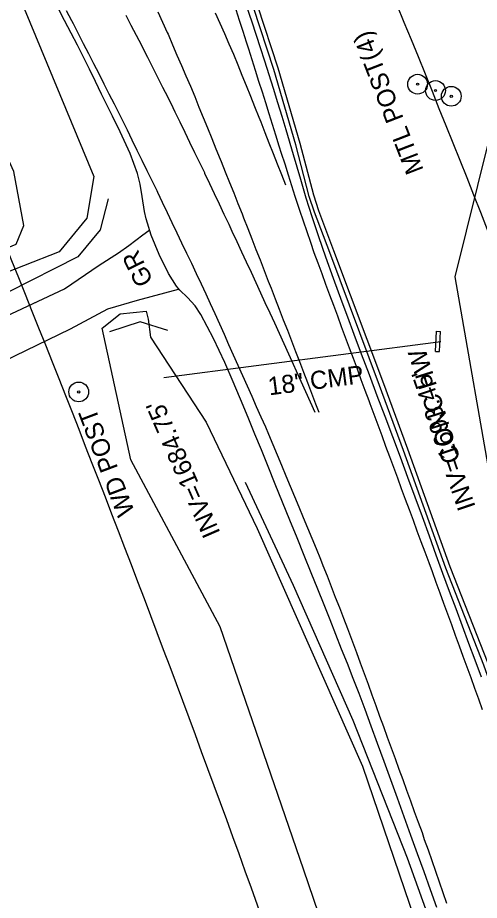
# Model space of a CAD drawing. Extents: x 472260 to 482161, y 489063 to 507124.
# Drawn here: x 480949.2 to 481051, y 492689.3 to 492884.2 of the extents above; entities that cross this region are included whole.
import ezdxf

# ---------------------------------------------------------------- set-up
doc = ezdxf.new("R2010")
doc.units = 0
for name, color, linetype in [('Exist Structure Minor Drop Inlet Cogo Elevation', 7, 'Continuous'), ('Exist Structure Minor Pipes CMP 30 Inch', 7, 'Continuous'), ('Prop Drainage Structure Catch Basin Convert From Junction Box Label', 7, 'Continuous'), ('Prop Drainage Structure Drop Inlet Grate 2 Narrow Slots and Sag Grates 840 24 CELL', 7, 'Continuous'), ('Prop Drainage Structure Pipe RCP 18in Class III', 7, 'Continuous'), ('Prop Drainage Structure Pipe RCP 30in Class III', 7, 'Continuous'), ('Prop Drainage Structure Pipe RCP 66in Class IV', 7, 'Continuous'), ('Prop Drainage Structure Pipe RCP 66in Class IV Label', 7, 'Continuous'), ('Prop Drainage Structure Pipe RCP 72in Class III', 7, 'Continuous'), ('Prop Drainage Structure Pipe Stub Out CELL', 7, 'Continuous'), ('Prop Drainage Structure Pipe Welded Steel 72in Label', 7, 'Continuous'), ('Prop Drainage Structure Plot Symbol 20 Scale CELL', 7, 'Continuous'), ('Prop Drainage Structure Plot Symbol 50 Scale', 7, 'Continuous'), ('Prop Drainage Structure Plot Symbol 50 Scale CELL', 7, 'Continuous'), ('Prop Drainage Structure Tops and Inverts LABEL', 7, 'Continuous'), ('Prop Earthen Structure False Sump Label', 7, 'Continuous'), ('Prop Erosion Rip Rap Pad at Outlet Label', 7, 'Continuous')]:
    doc.layers.add(name, color=color, linetype=linetype)

msp = doc.modelspace()

# ---------------------------------------------------------------- linework, layer by layer
at = {"layer": 'Exist Structure Minor Drop Inlet Cogo Elevation'}
for radius in [3954.58, 3854.58]:
    msp.add_arc((477373.51, 491387.79), radius, 18.70399, 22.51531, dxfattribs=at)
at = {"layer": 'Prop Drainage Structure Catch Basin Convert From Junction Box Label'}
for points in [[(481010.55, 492856.1), (481005.68, 492872.7), (481001.19, 492886.38), (480997.42, 492897.8), (480991.82, 492911.64), (480986.19, 492925.13), (480980.52, 492938.19), (480975.01, 492949.7), (480968.57, 492962.71), (480963.05, 492972.48), (480958.15, 492980.77), (480950.82, 492991.98), (480939.98, 493008.84), (480927.18, 493026.88)], [(481011.51, 492856.38), (481006.63, 492872.99), (481002.14, 492886.69), (480998.36, 492898.14), (480992.74, 492912.02), (480987.11, 492925.52), (480981.43, 492938.61), (480975.91, 492950.13), (480969.46, 492963.18), (480963.91, 492972.98), (480959, 492981.3), (480951.66, 492992.52), (480940.81, 493009.4), (480929.67, 493025.1)], [(481161.88, 492420.66), (481155.74, 492438.52), (481140.65, 492483.95), (481128.4, 492520.35), (481115.63, 492558.71), (481105.51, 492588.85), (481093.17, 492625.43), (481084.14, 492652.32), (481071.54, 492688.73), (481063.8, 492710.99), (481052.94, 492741.58), (481044.61, 492762.94), (481035.26, 492788.9), (481029.93, 492803.33), (481018.96, 492832.67), (481015.61, 492841.54), (481014.49, 492844.96), (481011.51, 492856.38)], [(481130.21, 492511.53), (481127.45, 492520.03), (481114.68, 492558.39), (481104.56, 492588.53), (481092.22, 492625.11), (481083.19, 492652), (481070.59, 492688.41), (481062.85, 492710.66), (481052, 492741.23), (481043.67, 492762.58), (481034.33, 492788.56), (481029, 492802.98), (481018.03, 492832.32), (481014.67, 492841.21), (481013.53, 492844.68), (481010.55, 492856.1)]]:
    msp.add_lwpolyline(points, dxfattribs=at)
at = {"layer": 'Prop Drainage Structure Drop Inlet Grate 2 Narrow Slots and Sag Grates 840 24 CELL'}
for points in [[(481043.89, 492688.55), (481043.07, 492690.9), (481042.25, 492693.25), (481041.43, 492695.6), (481040.61, 492697.96), (481039.79, 492700.31), (481038.97, 492702.66), (481038.46, 492704.14), (481037.61, 492706.48), (481036.76, 492708.82), (481035.91, 492711.16), (481035.06, 492713.51), (481034.21, 492715.85), (481033.36, 492718.19), (481032.51, 492720.53), (481031.65, 492722.87), (481030.8, 492725.21), (481029.95, 492727.55), (481029.1, 492729.89), (481028.25, 492732.23), (481027.4, 492734.58), (481026.55, 492736.92), (481025.7, 492739.26), (481024.85, 492741.6), (481024, 492743.94), (481023.15, 492746.28), (481022.93, 492746.88), (481022.03, 492749.2), (481021.13, 492751.52), (481020.23, 492753.85), (481019.32, 492756.17), (481018.42, 492758.49), (481017.52, 492760.81), (481016.62, 492763.13), (481016.07, 492764.54), (481015.11, 492766.85), (481014.15, 492769.15), (481013.2, 492771.45), (481012.24, 492773.75), (481011.29, 492776.05), (481010.33, 492778.35), (481009.37, 492780.66), (481008.42, 492782.96), (481007.46, 492785.26), (481006.5, 492787.56), (481005.55, 492789.86), (481004.59, 492792.16), (481003.95, 492793.71), (481002.93, 492795.99), (481001.91, 492798.26), (481000.89, 492800.54), (480999.88, 492802.81), (480998.86, 492805.09), (480997.84, 492807.36), (480996.83, 492809.64), (480995.81, 492811.91), (480994.79, 492814.19), (480993.77, 492816.46), (480992.76, 492818.74), (480991.74, 492821.01), (480990.81, 492823.1), (480989.73, 492825.35), (480988.66, 492827.6), (480987.59, 492829.85), (480986.52, 492832.1), (480985.45, 492834.34), (480984.38, 492836.59), (480983.31, 492838.84), (480982.24, 492841.09), (480981.16, 492843.34), (480980.09, 492845.59), (480979.95, 492845.9), (480978.85, 492848.14), (480977.76, 492850.37), (480976.67, 492852.61), (480975.58, 492854.85), (480974.49, 492857.09), (480973.4, 492859.33), (480972.3, 492861.57), (480971.68, 492862.85), (480970.55, 492865.07), (480969.41, 492867.29), (480968.28, 492869.51), (480967.15, 492871.73), (480966.02, 492873.95), (480964.89, 492876.17), (480963.75, 492878.38), (480962.62, 492880.6), (480961.49, 492882.82), (480961.15, 492883.48), (480959.95, 492885.66)], [(480980.12, 492885.47), (480981.15, 492883.2), (480982.17, 492880.93), (480982.37, 492880.49), (480983.36, 492878.19), (480984.34, 492875.9), (480985.32, 492873.61), (480986.31, 492871.32), (480987.29, 492869.03), (480988.27, 492866.75), (480989.2, 492864.44), (480990.14, 492862.13), (480991.08, 492859.82), (480992.01, 492857.51), (480992.95, 492855.2), (480993.88, 492852.89), (480994.08, 492852.42), (480995, 492850.11), (480995.92, 492847.79), (480996.85, 492845.48), (480997.77, 492843.16), (480998.7, 492840.85), (480999.05, 492839.96), (480999.96, 492837.64), (481000.86, 492835.31), (481001.77, 492832.99), (481002.67, 492830.67), (481003.57, 492828.34), (481004.48, 492826.02), (481005.1, 492824.44), (481006, 492822.11), (481006.9, 492819.79), (481007.8, 492817.46), (481008.7, 492815.14), (481009.6, 492812.81), (481010.51, 492810.49), (481011.37, 492808.25), (481012.26, 492805.92), (481013.15, 492803.59), (481014.04, 492801.26), (481014.92, 492798.93), (481015.64, 492797.04)], [(480997.32, 492885.97), (480998.09, 492883.6), (480998.85, 492881.22), (480999.62, 492878.85), (481000.12, 492877.32), (481000.87, 492874.94), (481001.61, 492872.56), (481002.36, 492870.18), (481003.1, 492867.8), (481003.85, 492865.42), (481004.59, 492863.04), (481005.34, 492860.66), (481006.08, 492858.28), (481006.83, 492855.89), (481007.34, 492854.25), (481008.1, 492851.87), (481008.86, 492849.49), (481009.61, 492847.12), (481010.37, 492844.74), (481011.12, 492842.36), (481011.34, 492841.68), (481012.15, 492839.32), (481012.95, 492836.96), (481013.76, 492834.6), (481014.53, 492832.34), (481015.39, 492830), (481016.26, 492827.67), (481017.13, 492825.33), (481017.99, 492822.99), (481018.86, 492820.65), (481019.73, 492818.31), (481020.59, 492815.97), (481021.46, 492813.63), (481022.32, 492811.3), (481023.19, 492808.96), (481024.06, 492806.62), (481024.92, 492804.28), (481025.79, 492801.94), (481026.66, 492799.6), (481026.9, 492798.94), (481027.77, 492796.6), (481028.63, 492794.26), (481029.49, 492791.92), (481030.36, 492789.58), (481031.22, 492787.24), (481032.09, 492784.9), (481032.95, 492782.56), (481033.81, 492780.22), (481034.68, 492777.88), (481035.54, 492775.55), (481036.41, 492773.21), (481037.27, 492770.87), (481038.14, 492768.53), (481039, 492766.19), (481039.86, 492763.85), (481040.59, 492761.88), (481041.44, 492759.54), (481042.3, 492757.2), (481043.15, 492754.86), (481044, 492752.52), (481044.86, 492750.17), (481045.71, 492747.83), (481046.56, 492745.49), (481047.42, 492743.15), (481048.27, 492740.8), (481049.12, 492738.46), (481049.98, 492736.12), (481050.83, 492733.78), (481051.68, 492731.44)], [(481014.79, 492797.02), (481013.77, 492799.3), (481012.75, 492801.57), (481011.74, 492803.85), (481010.72, 492806.12), (481010.05, 492807.62), (481009.01, 492809.89), (481007.98, 492812.15), (481006.94, 492814.42), (481005.91, 492816.68), (481004.87, 492818.95), (481003.83, 492821.22), (481002.85, 492823.37), (481001.8, 492825.63), (481000.75, 492827.89), (480999.7, 492830.15), (480998.65, 492832.41), (480997.6, 492834.67), (480996.55, 492836.93), (480995.84, 492838.48), (480994.78, 492840.73), (480993.71, 492842.98), (480992.65, 492845.24), (480991.59, 492847.49), (480990.52, 492849.74), (480990.46, 492849.87), (480989.38, 492852.11), (480988.29, 492854.35), (480987.21, 492856.6), (480986.12, 492858.84), (480985.04, 492861.08), (480983.95, 492863.33), (480983.49, 492864.28), (480982.37, 492866.51), (480981.25, 492868.73), (480980.13, 492870.96), (480979, 492873.18), (480977.88, 492875.4), (480976.76, 492877.63), (480976.58, 492877.99), (480975.42, 492880.2), (480974.27, 492882.41), (480973.11, 492884.62)], [(481008.36, 492847.15), (481007.45, 492849.47), (481006.54, 492851.79), (481005.62, 492854.11), (481004.71, 492856.43), (481003.8, 492858.75), (481002.88, 492861.07), (481002.47, 492862.13), (481001.54, 492864.45), (481000.61, 492866.76), (480999.68, 492869.08), (480998.75, 492871.39), (480997.83, 492873.71), (480996.88, 492876.05), (480995.87, 492878.34), (480994.87, 492880.62), (480993.86, 492882.9), (480992.85, 492885.18)]]:
    msp.add_lwpolyline(points, dxfattribs=at)
at = {"layer": 'Prop Drainage Structure Pipe RCP 18in Class III'}
for points in [[(480971.46, 492832.22), (480973.7, 492833.83), (480976.82, 492836.21), (480978.15, 492837.18)], [(480834.87, 492771.53), (480840.55, 492773.82), (480848.56, 492777.43), (480856.84, 492781.47), (480867, 492786.25), (480881.95, 492792.54), (480895.21, 492798.25), (480910.39, 492803.87), (480922.36, 492808.33), (480936.91, 492813.83), (480946.64, 492818.22), (480959.55, 492824.32), (480967.21, 492829.54), (480971.46, 492832.22)], [(480984.63, 492824.12), (480975.58, 492821.69)], [(480975.58, 492821.69), (480969.05, 492819.78), (480960.81, 492815.39), (480946.05, 492808.24), (480932.6, 492802.73), (480915.65, 492797.03), (480899.26, 492791.61), (480885.53, 492786.06), (480876.07, 492781.56), (480866.73, 492776.38), (480854.01, 492768.4)]]:
    msp.add_lwpolyline(points, dxfattribs=at)
at = {"layer": 'Prop Drainage Structure Pipe RCP 66in Class IV'}
msp.add_line((480981.44, 492804.69), (481042.53, 492812.66), dxfattribs=at)
at = {"layer": 'Prop Drainage Structure Pipe RCP 72in Class III'}
for points in [[(480969.15, 492844.19), (480967.38, 492837.31), (480962.49, 492831.38), (480947.15, 492823.58), (480935.93, 492819.13)], [(480982.3, 492815.09), (480976.24, 492817), (480969.46, 492814.82)]]:
    msp.add_lwpolyline(points, dxfattribs=at)
at = {"layer": 'Prop Drainage Structure Pipe Stub Out CELL'}
for points in [[(480999, 492888.65), (481000.83, 492883.24), (481002.68, 492877.56), (481003.62, 492874.62), (481004.57, 492871.63), (481005.53, 492868.58), (481006.51, 492865.47), (481007.45, 492862.4), (481008.35, 492859.46), (481009.98, 492853.95), (481011.56, 492848.49), (481012.79, 492844.39), (481014.07, 492840.25), (481015.53, 492835.84), (481017.11, 492831.36), (481018.81, 492826.63), (481020.72, 492821.39), (481021.94, 492818.09), (481023.37, 492814.28), (481025, 492809.94), (481026.73, 492805.34), (481028.45, 492800.77), (481030.17, 492796.21), (481031.87, 492791.68), (481033.56, 492787.18), (481035.2, 492782.73), (481036.82, 492778.33), (481038.39, 492773.99), (481039.93, 492769.73), (481041.45, 492765.57), (481042.93, 492761.51), (481044.38, 492757.56), (481045.81, 492753.69), (481047.23, 492749.86), (481048.63, 492746.08), (481050.02, 492742.35), (481051.4, 492738.65)], [(481041.65, 492687.71), (481040.26, 492691.59), (481038.83, 492695.54), (481037.39, 492699.54), (481035.92, 492703.6), (481034.44, 492707.71), (481032.96, 492711.83), (481031.49, 492715.89), (481030.04, 492719.91), (481028.6, 492723.88), (481027.19, 492727.74), (481025.82, 492731.43), (481024.49, 492734.94), (481023.2, 492738.28), (481021.93, 492741.53), (481020.66, 492744.76), (481019.39, 492747.99), (481018.11, 492751.21), (481016.8, 492754.51), (481015.41, 492757.97), (481013.94, 492761.6), (481012.4, 492765.39), (481010.82, 492769.28), (481009.23, 492773.21), (481007.63, 492777.16), (481006.02, 492781.15), (481004.45, 492785.05), (481002.95, 492788.74), (481001.52, 492792.21), (481000.17, 492795.48), (480998.91, 492798.5), (480996.7, 492803.74), (480994.87, 492807.99), (480992.37, 492813.34), (480989.64, 492818.66), (480988.33, 492820.54), (480986.7, 492822.4), (480985.01, 492824.02), (480984.27, 492824.9), (480982.51, 492827.7), (480980.44, 492831.88), (480978.68, 492836.14), (480977.52, 492839.73), (480977.15, 492841.38), (480976.7, 492844.71), (480976.23, 492847.44), (480975.65, 492849.79), (480974.01, 492854.17), (480971.82, 492858.95), (480970.12, 492862.44), (480967.73, 492867.31), (480966.37, 492870.07), (480965.02, 492872.78), (480962.38, 492878.06), (480961.01, 492880.73), (480959.55, 492883.57), (480957.97, 492886.57)]]:
    msp.add_lwpolyline(points, dxfattribs=at)
at = {"layer": 'Prop Drainage Structure Plot Symbol 20 Scale CELL'}
for centre, radius in [((481037.42, 492869.48), 2.18), ((481041.36, 492868.08), 2.18), ((481037.42, 492869.48), 0.24), ((481041.36, 492868.08), 0.24), ((481044.84, 492866.81), 2.18), ((481044.84, 492866.81), 0.24), ((480962.68, 492801.53), 2.18), ((480962.68, 492801.53), 0.24)]:
    msp.add_circle(centre, radius, dxfattribs=at)
at = {"layer": 'Prop Drainage Structure Plot Symbol 50 Scale'}
for p, q in [((481041.39, 492810.46), (481041.61, 492814.91)), ((481041.61, 492814.91), (481042.44, 492814.87)), ((481042.22, 492810.42), (481042.44, 492814.87)), ((481041.39, 492810.46), (481042.22, 492810.42))]:
    msp.add_line(p, q, dxfattribs=at)
at = {"layer": 'Prop Drainage Structure Plot Symbol 50 Scale CELL'}
msp.add_lwpolyline([(481159.92, 492332.85), (481147.67, 492369.02), (481136.31, 492402.63), (481122.19, 492443.94), (481109.37, 492481.77), (481096.99, 492518.51), (481082.03, 492563.66), (481066.9, 492608.24), (481049.63, 492658.22), (481035.22, 492698.61), (481023.2, 492728.97), (481010.06, 492758.78), (480999.42, 492781.5)], dxfattribs=at)
at = {"layer": 'Prop Drainage Structure Tops and Inverts LABEL'}
for points in [[(480941.52, 492831.11), (480948.88, 492834.16), (480950.54, 492838.31), (480948.36, 492850.21), (480929.77, 492891.42), (480918.34, 492912.08), (480925.79, 492919.02), (480932.4, 492916.78), (480949.38, 492889.32), (480965.99, 492849.1), (480964.5, 492839.91), (480958.38, 492832.46), (480942.57, 492826.26)], [(481080.2, 492471.74), (481071.23, 492513.93), (481054.53, 492571.95), (481012.28, 492696.13), (480993.86, 492749.69), (480974.19, 492786.51), (480967.88, 492815.61), (480971.79, 492818.74), (480977.52, 492819.35), (480978.02, 492817.58), (480978.51, 492813.62), (480990.77, 492794.88), (481002, 492771.37), (481025.27, 492718.92), (481050.65, 492644.35), (481078.23, 492565.63), (481100.49, 492496.39), (481097.57, 492474.75)]]:
    msp.add_lwpolyline(points, dxfattribs=at)
at = {"layer": 'Prop Erosion Rip Rap Pad at Outlet Label'}
msp.add_lwpolyline([(481200.38, 492382.62), (481135.69, 492556.19), (481093.4, 492673.11), (481070.04, 492725.37), (481054.31, 492777.66), (481045.71, 492826.93), (481053.22, 492857.22)], dxfattribs=at)

# ---------------------------------------------------------------- texts
at = {"layer": 'Exist Structure Minor Pipes CMP 30 Inch'}
msp.add_text('CONC HW', height=4, rotation=107.5706, dxfattribs=at).set_placement((481046.93, 492786.47))
at = {"layer": 'Prop Drainage Structure Pipe RCP 30in Class III'}
for s, rotation, p in [('MTL POST(4)', 111.1617, (481038.79, 492850.54)), ('WD POST', 110.7342, (480975.09, 492774.97))]:
    msp.add_text(s, height=4, rotation=rotation, dxfattribs=at).set_placement(p)
at = {"layer": 'Prop Drainage Structure Pipe RCP 66in Class IV Label'}
msp.add_text('18" CMP', height=4, rotation=7.4317, dxfattribs=at).set_placement((481004.69, 492800.76))
at = {"layer": 'Prop Drainage Structure Pipe Welded Steel 72in Label'}
for s, rotation, p in [("INV=1693.45'", 108.8744, (481050.24, 492776.15)), ("INV=1684.75'", 113.5599, (480993.98, 492770.41))]:
    msp.add_text(s, height=4, rotation=rotation, dxfattribs=at).set_placement(p)
at = {"layer": 'Prop Earthen Structure False Sump Label'}
msp.add_text('GR', height=4, rotation=116.5228, dxfattribs=at).set_placement((480979.22, 492826.02))

doc.saveas('drawing.dxf')
